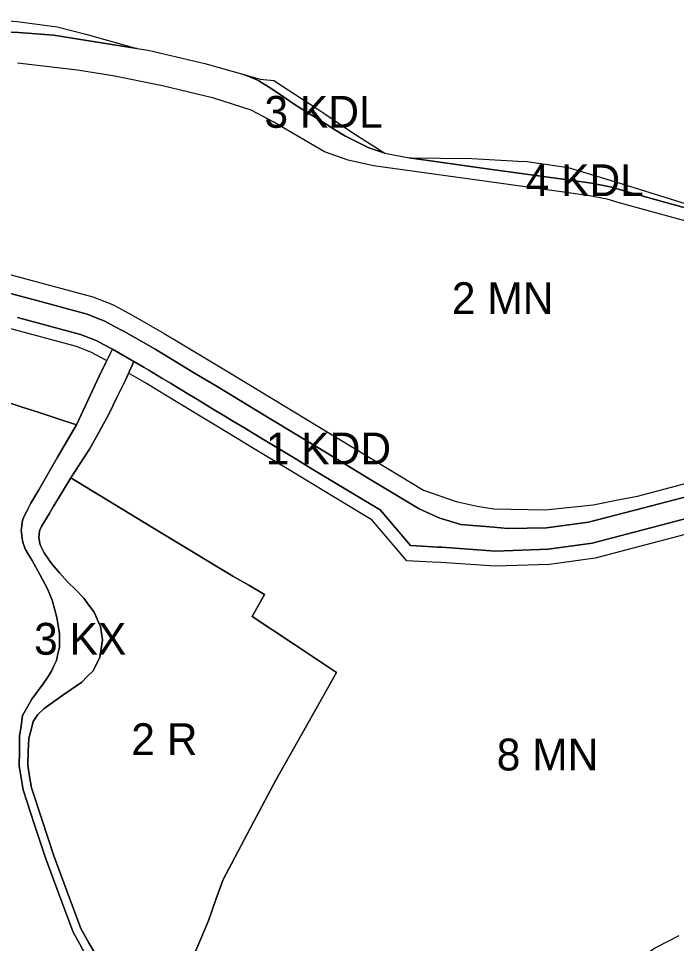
# Model space of a CAD drawing. Extents: x 7422252 to 7424226, y 5538569 to 5540380.
# Drawn here: x 7423473.1 to 7423783.3, y 5539103.9 to 5539539.7 of the extents above; entities that cross this region are included whole.
import ezdxf

# ---------------------------------------------------------------- set-up
doc = ezdxf.new("R2010")
doc.units = 0
for name, color, linetype in [('linie_rozgraniczajace', 7, 'Continuous'), ('linie_zabudowy_nieprzekraczalne', 7, 'Continuous'), ('oznaczenia_przeznaczen', 7, 'Continuous')]:
    doc.layers.add(name, color=color, linetype=linetype)

msp = doc.modelspace()

# ---------------------------------------------------------------- linework, layer by layer
at = {"layer": 'linie_rozgraniczajace'}
for points in [[(7423383.98, 5539533.39), (7423393.18, 5539536.72), (7423441.09, 5539538.46), (7423453.71, 5539539.65), (7423472.39, 5539538.27), (7423491.26, 5539535.75), (7423504.79, 5539532.3), (7423528.83, 5539525.52), (7423509.19, 5539528.69), (7423489.54, 5539531.86), (7423481.35, 5539532.46), (7423473.15, 5539533.05), (7423466.12, 5539533.33), (7423438.01, 5539533.58), (7423409.89, 5539533.83), (7423402.14, 5539525.64), (7423392.01, 5539525.41)], [(7423579.39, 5539513.24), (7423586.96, 5539511.07), (7423593.4, 5539510.47), (7423613.31, 5539497.62), (7423617.08, 5539495.07), (7423625.37, 5539489.48), (7423630.78, 5539485.84), (7423645.79, 5539476.23), (7423638.22, 5539478.71), (7423632.58, 5539481.53), (7423626.93, 5539484.35), (7423622.52, 5539487.1), (7423618.11, 5539489.86), (7423611.03, 5539494.28), (7423603.95, 5539498.7), (7423598.07, 5539502.69), (7423592.19, 5539506.67), (7423586.45, 5539510.35), (7423586.18, 5539510.46)], [(7423657.23, 5539474.02), (7423686.74, 5539473.68), (7423708.7, 5539472.45), (7423712.9, 5539472.22), (7423732.16, 5539469.42), (7423756.16, 5539462.25), (7423792.41, 5539451), (7423822.5, 5539442.43), (7423828.06, 5539440.87), (7423843.51, 5539437.03), (7423835.21, 5539438.46), (7423826.9, 5539439.88), (7423813.12, 5539443.52), (7423799.33, 5539447.16), (7423791.93, 5539449.21), (7423771.94, 5539454.76), (7423751.95, 5539460.31), (7423743.24, 5539462.01), (7423733.18, 5539463.45), (7423695.19, 5539468.74)]]:
    msp.add_lwpolyline(points, close=True, dxfattribs=at)
for points in [[(7423466.12, 5539533.33), (7423473.15, 5539533.05), (7423481.35, 5539532.46), (7423489.54, 5539531.86), (7423509.19, 5539528.69), (7423528.83, 5539525.52), (7423534.22, 5539524.74), (7423561.01, 5539518.49), (7423579.39, 5539513.24), (7423586.18, 5539510.46), (7423586.45, 5539510.35), (7423592.19, 5539506.67), (7423598.07, 5539502.69), (7423603.95, 5539498.7), (7423611.03, 5539494.28), (7423618.11, 5539489.86), (7423622.52, 5539487.1), (7423626.93, 5539484.35), (7423632.58, 5539481.53), (7423638.22, 5539478.71), (7423645.79, 5539476.23), (7423657.23, 5539474.02), (7423695.19, 5539468.74), (7423733.18, 5539463.45), (7423743.24, 5539462.01), (7423751.95, 5539460.31), (7423771.94, 5539454.76), (7423791.93, 5539449.21)], [(7423457.88, 5539413.14), (7423481.67, 5539406.73), (7423505.45, 5539400.32), (7423509.63, 5539398.67), (7423513.81, 5539397.02), (7423518.06, 5539394.78), (7423522.84, 5539392.25), (7423530.15, 5539388.08), (7423537.46, 5539383.91), (7423541.1, 5539381.71), (7423544.74, 5539379.51), (7423556.11, 5539372.63), (7423567.49, 5539365.76), (7423591.23, 5539351.41), (7423614.97, 5539337.06), (7423638.48, 5539322.85), (7423662, 5539308.64), (7423671.78, 5539304.32), (7423681.6, 5539301.28), (7423687.35, 5539300.78), (7423697.25, 5539299.97), (7423703.81, 5539299.43), (7423712.88, 5539299.54), (7423721.95, 5539299.65), (7423741.79, 5539302.38), (7423767.2, 5539308.99), (7423792.62, 5539315.59)], [(7423638.48, 5539322.85), (7423614.97, 5539337.06), (7423591.23, 5539351.41), (7423567.49, 5539365.76), (7423556.11, 5539372.63), (7423544.74, 5539379.51), (7423541.1, 5539381.71), (7423537.46, 5539383.91), (7423530.15, 5539388.08), (7423522.84, 5539392.25), (7423518.06, 5539394.78), (7423513.81, 5539397.02), (7423509.63, 5539398.67), (7423505.45, 5539400.32), (7423481.67, 5539406.73), (7423457.88, 5539413.14)], [(7423472.64, 5539398.81), (7423502.3, 5539390.81), (7423509.63, 5539387.92), (7423513.51, 5539385.87), (7423517.39, 5539383.82), (7423514.16, 5539377.35), (7423511.04, 5539371.09), (7423505.71, 5539359.66), (7423500.37, 5539348.22), (7423491.34, 5539351.19), (7423482.32, 5539354.16), (7423474.83, 5539356.61), (7423467.35, 5539359.07)], [(7423602.7, 5539332.8), (7423594.87, 5539337.53), (7423587.05, 5539342.25), (7423584.18, 5539343.98), (7423579.34, 5539346.91), (7423574.49, 5539349.84), (7423569.64, 5539352.77), (7423565.39, 5539355.34), (7423557.44, 5539360.15), (7423553.75, 5539362.38), (7423549.26, 5539365.09), (7423544.76, 5539367.81), (7423540.64, 5539370.3), (7423536.52, 5539372.79), (7423534.46, 5539374.04), (7423532.4, 5539375.28), (7423527.42, 5539378.12), (7423517.39, 5539383.82), (7423513.51, 5539385.87), (7423509.63, 5539387.92), (7423502.3, 5539390.81), (7423472.64, 5539398.81)], [(7423473.42, 5539187.64), (7423473.49, 5539194.62), (7423473.57, 5539201.6), (7423474.31, 5539206.47), (7423475.05, 5539211.34), (7423479.33, 5539219.08), (7423482.02, 5539222.64), (7423484.71, 5539226.2), (7423486.71, 5539229.2), (7423488.7, 5539232.19), (7423489.82, 5539234.71), (7423490.93, 5539237.23), (7423491.65, 5539240.38), (7423492.37, 5539243.54), (7423492.41, 5539246.68), (7423492.45, 5539249.82), (7423491.82, 5539253.67), (7423491.19, 5539257.51), (7423490.07, 5539261.59), (7423488.94, 5539265.68), (7423487.82, 5539268.37), (7423486.7, 5539271.06), (7423483.11, 5539277.73), (7423479.53, 5539284.39), (7423477.96, 5539286.92), (7423476.4, 5539289.44), (7423475.68, 5539291.56), (7423474.96, 5539293.67), (7423474.68, 5539296.16), (7423474.4, 5539298.66), (7423474.59, 5539300.57), (7423474.78, 5539302.48), (7423475.48, 5539304.57), (7423477.22, 5539307.92), (7423478.96, 5539311.27), (7423480.79, 5539314.47), (7423482.62, 5539317.67), (7423491.49, 5539332.95), (7423500.37, 5539348.22), (7423505.71, 5539359.66), (7423511.04, 5539371.09), (7423514.16, 5539377.35), (7423517.39, 5539383.82), (7423527.42, 5539378.12), (7423523.37, 5539368.92), (7423519.52, 5539361.11), (7423515.67, 5539353.3), (7423511.1, 5539345.01), (7423506.53, 5539336.72), (7423503.95, 5539332.77), (7423497.74, 5539323.24), (7423493.6, 5539316.45), (7423489.45, 5539309.66), (7423487.5, 5539306.28), (7423483.92, 5539300.36), (7423483, 5539298.34), (7423482.72, 5539294.97), (7423483.3, 5539291.75), (7423484.23, 5539289.87), (7423485.15, 5539288), (7423488.61, 5539282.89), (7423492.42, 5539278.57), (7423496.22, 5539274.25), (7423500.06, 5539270.45), (7423503.9, 5539266.65), (7423506.32, 5539263.32), (7423508.74, 5539259.99), (7423510.24, 5539256.64), (7423511.74, 5539253.3), (7423512.19, 5539250.1), (7423512.65, 5539246.9), (7423511.41, 5539238.66), (7423508.09, 5539232.26), (7423505.48, 5539229.67), (7423502.88, 5539227.07), (7423494.05, 5539220.87), (7423485.22, 5539214.66), (7423482.25, 5539211.8), (7423480.03, 5539208.51), (7423479.01, 5539204.59), (7423477.98, 5539200.68), (7423477.7, 5539194.31), (7423477.42, 5539187.94), (7423478.29, 5539182.61), (7423479.15, 5539177.28), (7423484.37, 5539161.47), (7423489.59, 5539145.66), (7423496.02, 5539128.29), (7423502.45, 5539110.91), (7423506.31, 5539104.18), (7423510.17, 5539097.45)], [(7423497.74, 5539323.24), (7423503.95, 5539332.77), (7423506.53, 5539336.72), (7423511.1, 5539345.01), (7423515.67, 5539353.3), (7423519.52, 5539361.11), (7423523.37, 5539368.92), (7423527.42, 5539378.12), (7423532.4, 5539375.28), (7423534.46, 5539374.04), (7423536.52, 5539372.79), (7423540.64, 5539370.3), (7423544.76, 5539367.81), (7423549.26, 5539365.09), (7423553.75, 5539362.38), (7423557.44, 5539360.15), (7423565.39, 5539355.34), (7423569.64, 5539352.77), (7423574.49, 5539349.84), (7423579.34, 5539346.91), (7423584.18, 5539343.98), (7423587.05, 5539342.25), (7423594.87, 5539337.53), (7423602.7, 5539332.8), (7423607.28, 5539330.02), (7423611.87, 5539327.25), (7423618.98, 5539322.96), (7423629.12, 5539316.83), (7423639.27, 5539310.69), (7423643.52, 5539308.12), (7423650.74, 5539299.72), (7423657.96, 5539291.32), (7423663.2, 5539291.05), (7423668.43, 5539290.78), (7423670.51, 5539290.67), (7423672.59, 5539290.56), (7423685.3, 5539289.66), (7423698.02, 5539288.76), (7423710.4, 5539289.18), (7423722.79, 5539289.6), (7423733.18, 5539291.06), (7423743.57, 5539292.52), (7423773.51, 5539300.39), (7423803.45, 5539308.26)], [(7423467.35, 5539359.07), (7423474.83, 5539356.61), (7423482.32, 5539354.16), (7423491.34, 5539351.19), (7423500.37, 5539348.22), (7423491.49, 5539332.95), (7423482.62, 5539317.67), (7423480.79, 5539314.47), (7423478.96, 5539311.27), (7423477.22, 5539307.92), (7423475.48, 5539304.57), (7423474.78, 5539302.48), (7423474.59, 5539300.57), (7423474.4, 5539298.66), (7423474.68, 5539296.16), (7423474.96, 5539293.67), (7423475.68, 5539291.56), (7423476.4, 5539289.44), (7423477.96, 5539286.92), (7423479.53, 5539284.39), (7423483.11, 5539277.73), (7423486.7, 5539271.06), (7423487.82, 5539268.37), (7423488.94, 5539265.68), (7423490.07, 5539261.59), (7423491.19, 5539257.51), (7423491.82, 5539253.67), (7423492.45, 5539249.82), (7423492.41, 5539246.68), (7423492.37, 5539243.54), (7423491.65, 5539240.38), (7423490.93, 5539237.23), (7423489.82, 5539234.71), (7423488.7, 5539232.19), (7423486.71, 5539229.2), (7423484.71, 5539226.2), (7423482.02, 5539222.64), (7423479.33, 5539219.08), (7423475.05, 5539211.34), (7423474.31, 5539206.47), (7423473.57, 5539201.6), (7423473.49, 5539194.62), (7423473.42, 5539187.64), (7423474.34, 5539181.98), (7423475.26, 5539176.32), (7423480.53, 5539160.33), (7423485.81, 5539144.34), (7423492.31, 5539126.77), (7423498.82, 5539109.21), (7423502.85, 5539102.19)], [(7423803.45, 5539308.26), (7423773.51, 5539300.39), (7423743.57, 5539292.52), (7423733.18, 5539291.06), (7423722.79, 5539289.6), (7423710.4, 5539289.18), (7423698.02, 5539288.76), (7423685.3, 5539289.66), (7423672.59, 5539290.56), (7423670.51, 5539290.67), (7423668.43, 5539290.78), (7423663.2, 5539291.05), (7423657.96, 5539291.32), (7423650.74, 5539299.72), (7423643.52, 5539308.12), (7423639.27, 5539310.69), (7423629.12, 5539316.83), (7423618.98, 5539322.96), (7423611.87, 5539327.25), (7423607.28, 5539330.02), (7423602.7, 5539332.8)], [(7423510.17, 5539097.45), (7423506.31, 5539104.18), (7423502.45, 5539110.91), (7423496.02, 5539128.29), (7423489.59, 5539145.66), (7423484.37, 5539161.47), (7423479.15, 5539177.28), (7423478.29, 5539182.61), (7423477.42, 5539187.94), (7423477.7, 5539194.31), (7423477.98, 5539200.68), (7423479.01, 5539204.59), (7423480.03, 5539208.51), (7423482.25, 5539211.8), (7423485.22, 5539214.66), (7423494.05, 5539220.87), (7423502.88, 5539227.07), (7423505.48, 5539229.67), (7423508.09, 5539232.26), (7423511.41, 5539238.66), (7423512.65, 5539246.9), (7423512.19, 5539250.1), (7423511.74, 5539253.3), (7423510.24, 5539256.64), (7423508.74, 5539259.99), (7423506.32, 5539263.32), (7423503.9, 5539266.65), (7423500.06, 5539270.45), (7423496.22, 5539274.25), (7423492.42, 5539278.57), (7423488.61, 5539282.89), (7423485.15, 5539288), (7423484.23, 5539289.87), (7423483.3, 5539291.75), (7423482.72, 5539294.97), (7423483, 5539298.34), (7423483.92, 5539300.36), (7423487.5, 5539306.28), (7423489.45, 5539309.66), (7423493.6, 5539316.45), (7423497.74, 5539323.24), (7423535.94, 5539300.11), (7423574.13, 5539276.98), (7423581.63, 5539272.67), (7423589.13, 5539268.36), (7423583.26, 5539257.89), (7423603.16, 5539244.74), (7423623.07, 5539231.59), (7423608.79, 5539206.37), (7423594.5, 5539181.14), (7423584.04, 5539161.31), (7423573.58, 5539141.48), (7423569.53, 5539134.11), (7423566.15, 5539124.58), (7423562.77, 5539115.04), (7423559.06, 5539106.16), (7423555.35, 5539097.28)], [(7423555.35, 5539097.28), (7423559.06, 5539106.16), (7423562.77, 5539115.04), (7423566.15, 5539124.58), (7423569.53, 5539134.11), (7423573.58, 5539141.48), (7423584.04, 5539161.31), (7423594.5, 5539181.14), (7423608.79, 5539206.37), (7423623.07, 5539231.59), (7423603.16, 5539244.74), (7423583.26, 5539257.89), (7423589.13, 5539268.36), (7423581.63, 5539272.67), (7423574.13, 5539276.98), (7423535.94, 5539300.11), (7423497.74, 5539323.24)], [(7423792.62, 5539315.59), (7423767.2, 5539308.99), (7423741.79, 5539302.38), (7423721.95, 5539299.65), (7423712.88, 5539299.54), (7423703.81, 5539299.43), (7423697.25, 5539299.97), (7423687.35, 5539300.78), (7423681.6, 5539301.28), (7423671.78, 5539304.32), (7423662, 5539308.64), (7423638.48, 5539322.85)], [(7423521.09, 5539074.49), (7423516.1, 5539079.22), (7423512.53, 5539084.37), (7423509.71, 5539089.77), (7423506.88, 5539095.16), (7423502.85, 5539102.19), (7423498.82, 5539109.21), (7423492.31, 5539126.77), (7423485.81, 5539144.34), (7423480.53, 5539160.33), (7423475.26, 5539176.32), (7423474.34, 5539181.98), (7423473.42, 5539187.64)]]:
    msp.add_lwpolyline(points, dxfattribs=at)
at = {"layer": 'linie_zabudowy_nieprzekraczalne'}
for points in [[(7423806.71, 5539439.01), (7423756.27, 5539452.89), (7423750.57, 5539454.47), (7423742.24, 5539456.09), (7423732.34, 5539457.51), (7423693.86, 5539462.87), (7423640.5, 5539470.31), (7423628.43, 5539472.98), (7423617.39, 5539476.87), (7423593.45, 5539490.74), (7423593.45, 5539490.74), (7423582.83, 5539496.49), (7423565.15, 5539502.15), (7423565.15, 5539502.15), (7423540.93, 5539507.97), (7423540.93, 5539507.97), (7423517.63, 5539512.57), (7423517.63, 5539512.57), (7423500.91, 5539515.27), (7423500.91, 5539515.27), (7423500.91, 5539515.27), (7423472.54, 5539518.68)], [(7423460.12, 5539421.46), (7423508.16, 5539408.52), (7423517.42, 5539404.87), (7423522.09, 5539402.4), (7423526.99, 5539399.81), (7423541.83, 5539391.34), (7423549.2, 5539386.89), (7423571.95, 5539373.14), (7423619.43, 5539344.44), (7423664.03, 5539317.49), (7423679.37, 5539312.06), (7423689.26, 5539309.98), (7423689.26, 5539309.98), (7423697.24, 5539308.68), (7423697.24, 5539308.68), (7423721.31, 5539308.26), (7423744.04, 5539310.61), (7423756.46, 5539313.04), (7423764.98, 5539314.61), (7423818.79, 5539328.98)], [(7423514.71, 5539378.45), (7423514.58, 5539378.52), (7423507.12, 5539382.46), (7423500.42, 5539385.11), (7423441.42, 5539401), (7423425.97, 5539405.17), (7423411.23, 5539406.96), (7423405.47, 5539407.09), (7423398.43, 5539406.35), (7423385.75, 5539403.81), (7423292.97, 5539378.24)], [(7423805.3, 5539301.34), (7423744.98, 5539285.49), (7423723.41, 5539282.45), (7423697.88, 5539281.59), (7423672.16, 5539283.41), (7423668.06, 5539283.62), (7423656.14, 5539284.24), (7423639.6, 5539303.49), (7423636.16, 5539305.56), (7423615.87, 5539317.82), (7423608.77, 5539322.12), (7423599.59, 5539327.66), (7423583.94, 5539337.12), (7423576.23, 5539341.78), (7423566.54, 5539347.64), (7423558.02, 5539352.78), (7423550.65, 5539357.24), (7423541.66, 5539362.67), (7423533.42, 5539367.66), (7423529.36, 5539370.11), (7423524.99, 5539372.6)], [(7423545.17, 5539073.71), (7423571.32, 5539055.98), (7423601.74, 5539035.36), (7423621.93, 5539022.48), (7423621.93, 5539022.48), (7423641.78, 5539018), (7423664.16, 5539025.1), (7423664.16, 5539025.1), (7423673.43, 5539028.83), (7423673.43, 5539028.83), (7423685.01, 5539036.01), (7423704.38, 5539050.76), (7423704.38, 5539050.76), (7423727.38, 5539068.41), (7423727.38, 5539068.41), (7423756.01, 5539090.35), (7423756.01, 5539090.35), (7423763.01, 5539095.09), (7423773.26, 5539101.85), (7423784.55, 5539107.69)]]:
    msp.add_lwpolyline(points, dxfattribs=at)

# ---------------------------------------------------------------- texts
at = {"layer": 'oznaczenia_przeznaczen'}
for s, p in [('3 KDL', (7423589.03, 5539488.17)), ('4 KDL', (7423712.16, 5539455.96)), ('2 MN', (7423677.38, 5539400.39)), ('1 KDD', (7423589.67, 5539329.59)), ('3 KX', (7423480.43, 5539239.94)), ('2 R', (7423526.24, 5539192.65)), ('8 MN', (7423698.53, 5539185.43))]:
    msp.add_text(s, height=15, dxfattribs=at).set_placement(p)

doc.saveas('drawing.dxf')
